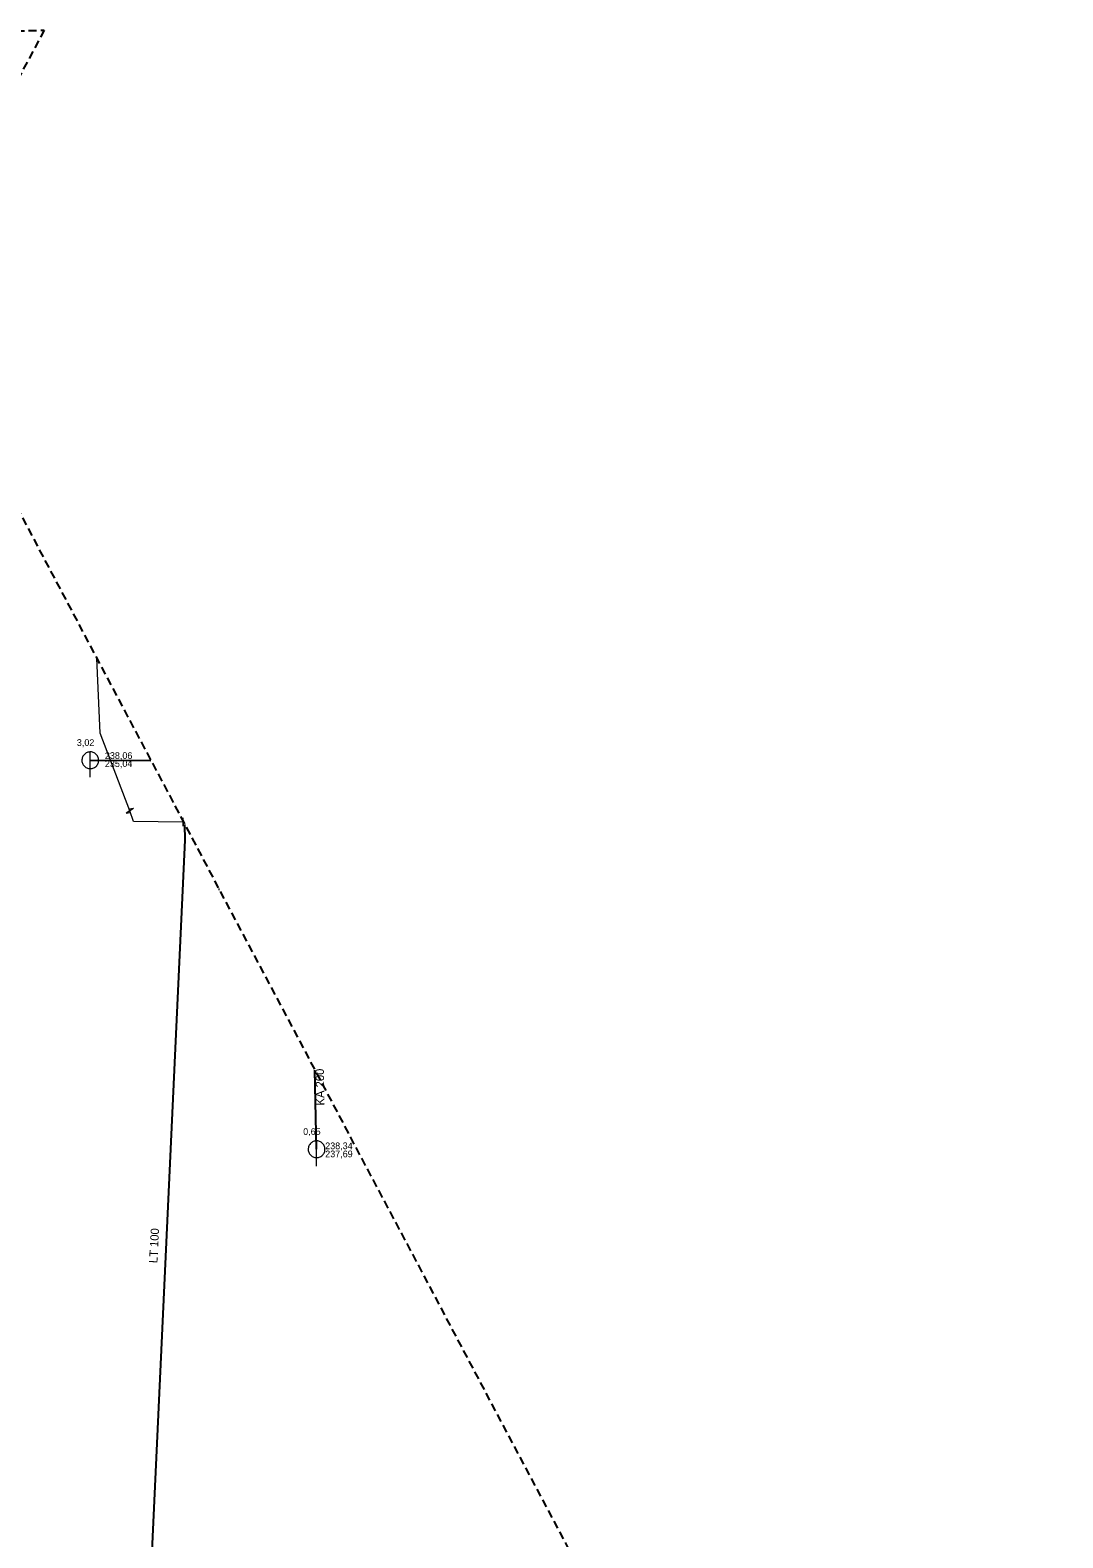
# Model space of a CAD drawing. Extents: x -777996 to -777727, y -976581 to -976199.
# Drawn here: x -777849.8 to -777726.8, y -976378.6 to -976198.8 of the extents above; entities that cross this region are included whole.
import ezdxf

# ---------------------------------------------------------------- set-up
doc = ezdxf.new("R2010")
doc.units = 0
doc.header["$LTSCALE"] = 0.32
doc.linetypes.add('MEDIUM_DASHED', pattern=[4.5, 3, -1.5])
for name, color, linetype, lineweight in [('1', 7, 'MEDIUM_DASHED', 25), ('13', 7, 'Continuous', 13), ('14', 7, 'Continuous', 25), ('17', 7, 'Continuous', 25), ('22', 7, 'Continuous', 13), ('34', 7, 'Continuous', 13), ('47', 7, 'Continuous', 13)]:
    doc.layers.add(name, color=color, linetype=linetype, lineweight=lineweight)

msp = doc.modelspace()

# ---------------------------------------------------------------- linework, layer by layer
at = {"layer": '1'}
msp.add_lwpolyline([(-777995.417, -976203.033), (-777848.18, -976198.846), (-777864.927, -976230.247), (-777726.762, -976491.225), (-777789.565, -976581.242), (-777941.686, -976558.215), (-777989.136, -976405.396)], close=True, dxfattribs=at)
at = {"layer": '13'}
msp.add_line((-777827.374, -976301.181), (-777827.368, -976301.374), dxfattribs=at)
for points in [[(-777837.987, -976291.92), (-777841.52, -976282.649), (-777841.912, -976273.721)], [(-777831.65, -976293.257), (-777837.526, -976293.182), (-777837.987, -976291.92)]]:
    msp.add_lwpolyline(points, dxfattribs=at)
at = {"layer": '14'}
for p, q in [((-777842.684, -976285.89), (-777835.464, -976285.901)), ((-777815.708, -976332.259), (-777815.912, -976322.832))]:
    msp.add_line(p, q, dxfattribs=at)
at = {"layer": '14', "lineweight": 13}
msp.add_line((-777831.569, -976293.257), (-777831.65, -976293.257), dxfattribs=at)
at = {"layer": '17'}
msp.add_lwpolyline([(-777835.78, -976390.413), (-777831.355, -976295.405), (-777831.422, -976293.534)], dxfattribs=at)
at = {"layer": '22'}
for p, q in [((-777842.684, -976287.89), (-777842.683, -976284.89)), ((-777815.708, -976334.259), (-777815.707, -976331.259))]:
    msp.add_line(p, q, dxfattribs=at)
for points in [[(-777841.684, -976285.89), (-777841.689, -976285.781), (-777841.707, -976285.673), (-777841.737, -976285.567), (-777841.777, -976285.466), (-777841.829, -976285.369), (-777841.891, -976285.279), (-777841.963, -976285.196), (-777842.043, -976285.122), (-777842.131, -976285.056), (-777842.225, -976285.001), (-777842.325, -976284.956), (-777842.43, -976284.923), (-777842.537, -976284.901), (-777842.646, -976284.891), (-777842.756, -976284.893), (-777842.864, -976284.907), (-777842.971, -976284.932), (-777843.074, -976284.969), (-777843.172, -976285.018), (-777843.264, -976285.076), (-777843.35, -976285.145), (-777843.427, -976285.222), (-777843.496, -976285.308), (-777843.555, -976285.4), (-777843.603, -976285.498), (-777843.64, -976285.601), (-777843.666, -976285.708), (-777843.68, -976285.816), (-777843.683, -976285.926), (-777843.673, -976286.035), (-777843.652, -976286.142), (-777843.618, -976286.246), (-777843.574, -976286.346), (-777843.519, -976286.441), (-777843.453, -976286.529), (-777843.379, -976286.609), (-777843.296, -976286.681), (-777843.206, -976286.743), (-777843.11, -976286.795), (-777843.008, -976286.836), (-777842.903, -976286.866), (-777842.795, -976286.884), (-777842.685, -976286.89), (-777842.576, -976286.884), (-777842.468, -976286.866), (-777842.363, -976286.837), (-777842.261, -976286.796), (-777842.164, -976286.744), (-777842.074, -976286.682), (-777841.991, -976286.611), (-777841.916, -976286.531), (-777841.851, -976286.443), (-777841.795, -976286.349), (-777841.751, -976286.249), (-777841.717, -976286.145), (-777841.695, -976286.037), (-777841.685, -976285.928)], [(-777814.708, -976332.259), (-777814.713, -976332.15), (-777814.731, -976332.042), (-777814.761, -976331.936), (-777814.801, -976331.835), (-777814.853, -976331.738), (-777814.915, -976331.648), (-777814.987, -976331.565), (-777815.067, -976331.491), (-777815.155, -976331.425), (-777815.249, -976331.37), (-777815.349, -976331.325), (-777815.454, -976331.292), (-777815.561, -976331.27), (-777815.67, -976331.26), (-777815.78, -976331.262), (-777815.888, -976331.276), (-777815.995, -976331.301), (-777816.098, -976331.338), (-777816.196, -976331.387), (-777816.288, -976331.445), (-777816.374, -976331.514), (-777816.451, -976331.591), (-777816.52, -976331.677), (-777816.579, -976331.769), (-777816.627, -976331.867), (-777816.664, -976331.97), (-777816.69, -976332.077), (-777816.704, -976332.185), (-777816.707, -976332.295), (-777816.697, -976332.404), (-777816.676, -976332.511), (-777816.642, -976332.615), (-777816.598, -976332.715), (-777816.543, -976332.81), (-777816.477, -976332.898), (-777816.403, -976332.978), (-777816.32, -976333.05), (-777816.23, -976333.112), (-777816.134, -976333.164), (-777816.032, -976333.205), (-777815.927, -976333.235), (-777815.819, -976333.253), (-777815.709, -976333.259), (-777815.6, -976333.253), (-777815.492, -976333.235), (-777815.387, -976333.206), (-777815.285, -976333.165), (-777815.188, -976333.113), (-777815.098, -976333.051), (-777815.015, -976332.98), (-777814.94, -976332.9), (-777814.875, -976332.812), (-777814.819, -976332.718), (-777814.775, -976332.618), (-777814.741, -976332.514), (-777814.719, -976332.406), (-777814.709, -976332.297)]]:
    msp.add_lwpolyline(points, close=True, dxfattribs=at)
at = {"layer": '34'}
msp.add_line((-777831.644, -976292.757), (-777831.656, -976293.756), dxfattribs=at)
at = {"layer": '47'}
msp.add_line((-777837.55, -976291.656), (-777838.055, -976291.731), dxfattribs=at)
msp.add_lwpolyline([(-777837.55, -976291.656), (-777838.423, -976292.183), (-777837.918, -976292.108)], dxfattribs=at)

# ---------------------------------------------------------------- texts
at = {"layer": '1'}
for s, p in [('3,02', (-777844.284, -976284.178)), ('0,65', (-777817.308, -976330.547))]:
    msp.add_text(s, height=0.8, dxfattribs=at).set_placement(p)
for s, rotation, p in [('KA 200', 91, (-777814.763, -976327.033)), ('LT 100', 87, (-777834.691, -976345.86))]:
    msp.add_text(s, height=1, rotation=rotation, dxfattribs=at).set_placement(p)
at = {"layer": '22'}
for s, p in [('238,06', (-777840.941, -976285.729)), ('235,04', (-777840.941, -976286.689)), ('238,34', (-777814.681, -976332.255)), ('237,69', (-777814.681, -976333.215))]:
    msp.add_text(s, height=0.8, dxfattribs=at).set_placement(p)

doc.saveas('drawing.dxf')
